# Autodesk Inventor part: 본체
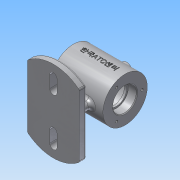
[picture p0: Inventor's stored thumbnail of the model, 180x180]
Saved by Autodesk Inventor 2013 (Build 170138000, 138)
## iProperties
Created: 2017-12
Part Number: 본체
Material: 알루미늄 6061
Document SubType Name: Modeling
Designer: Administrator
Density: 2.71 g/cm^3
Mass: 467.692 g
Surface Area: 486.473 cm^2
Volume: 172.58 cm^3
Author: Administrator
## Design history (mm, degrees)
sketch "스케치1"
  geometry: L1 (-35, 16)-(-23, 16); L2 (-23, 16)-(-23, 14); L3 (-23, 14)-(-20, 14); L4 (-20, 14)-(-20, 25); L5 (-20, 25)-(20, 25); L6 (20, 25)-(20, 14); L7 (20, 14)-(23, 14); L8 (23, 14)-(23, 16); L9 (23, 16)-(35, 16); L10 (35, 16)-(35, 30); L11 (35, 30)-(-35, 30); L12 (-35, 30)-(-35, 16); L13 (-49, 0)-(49, 0) reference; 1 further point
  constraints: 24 end point, 9 parallel, 1 collinear, 1 horizontal, 1 perpendicular
  dimensions: "d0" = 16 distance from line of L1 point (0, 0); "d1" = 14 distance from line of L3 point (0, 0); "d2" = 25 distance from line of L5 point (0, 0); "d3" = 14 distance from line of L7 point (0, 0); "d4" = 16 distance from line of L9 point (0, 0); "d5" = 70 distance of L10.end L11.end; "d6" = 12 distance of L1.start L1.end; "d7" = 3 distance of L2.end L3.end; "d8" = 40 distance of L4.end L5.end; "d9" = 3 distance of L6.end L7.end; "d10" = 30 distance from line of L11 point (0, 0); "d11" = 35 distance from line of L12 point (0, 0)
revolve "회전1" sketch "스케치1" stored, may be unused: angle "d12" = 90 deg
sketch "스케치2"
  geometry: C1 r 30 at (0, 0) reference; 1 further point
  constraints: 1 vertical alignment
  dimensions: "d13" = 23 distance of point (0, 23) C1.centre
hole "구멍1" sketch "스케치2" at (0, 23) diameter "d14" = 3.242; stored, may be unused: countersink angle "d18" = 90 deg, drill point angle "d20" = 118 deg; dims "d15" = 8, "d16" = 4, "d17" = 2, "d19" = 10
node "작업 평면1"
sketch "스케치3"
  geometry: C1 r 8 at (0, 0); 1 further point
  constraints: 1 centre point, 1 coincident
  dimensions: "d25" = 16 diameter of C1
extrude "돌출1" join sketch "스케치3" stored distance "d27" = 10; taper "d28" = 0 deg
hole "구멍2" diameter "d31" = 8; stored, may be unused: countersink angle "d35" = 90 deg, drill point angle "d37" = 118 deg; dims "d29" = 10, "d30" = 10, "d32" = 8, "d33" = 4, "d34" = 2, "d36" = 20
node "작업 평면2"
sketch "스케치4"
  geometry: L1 (35, 42.426)-(35, -42.426); L2 (-35, -42.426)-(-35, 42.426); C1 r 55 at (0, 0); A1 r 55 centre (0, 0) between (35, 42.426) and (-35, 42.426); A2 r 55 centre (0, 0) between (-35, -42.426) and (35, -42.426); 1 further point
  constraints: 4 end point, 4 point on circle, 3 centre point, 2 coincident, 1 parallel, 1 vertical
  dimensions: "d41" = 35 distance from line of L2 point (0, 0); "d42" = 70 distance between parallel lines of L1 L2; "d43" = 55 radius of A1; "d44" = 55 radius of A2; "d45" = 110 diameter of C1
extrude "돌출2" join sketch "스케치4" distance "d46" = 10; taper "d47" = 0 deg
sketch "스케치5"
  geometry: L1 (5, 40)-(5, 24); L2 (-5, 24)-(-5, 40); A1 r 55 centre (0, 0) between (-35, -42.426) and (35, -42.426) reference; A2 r 5 centre (0, 40) between (5, 40) and (-5, 40); A3 r 5 centre (0, 24) between (-5, 24) and (5, 24)
  constraints: 4 end point, 4 point on circle, 2 centre point, 2 tangent, 1 parallel, 1 vertical alignment
  dimensions: "d48" = 5 distance from line of L2 A1.centre; "d49" = 10 distance of L1.end L2.start; "d52" = 10 diameter of A2; "d53" = 10 diameter of A3; "d54" = 16 distance of A3.centre A2.centre; "d55" = 24 distance of A1.centre A3.centre
extrude "돌출3" cut sketch "스케치5" stored distance "d56" = 0; taper "d57" = 0 deg
sketch "스케치6"
  geometry: L1 (-15, 5)-(15, 5); L2 (15, -5)-(-15, -5); A1 r 55 centre (0, 0) between (-35, -42.426) and (35, -42.426) reference; A2 r 5 centre (-15, 0) between (-15, 5) and (-15, -5); A3 r 5 centre (15, 0) between (15, -5) and (15, 5)
  constraints: 4 end point, 4 point on circle, 2 centre point, 2 tangent, 1 horizontal, 1 parallel
  dimensions: "d61" = 10 distance of L2.end L1.start; "d62" = 5 distance from line of L1 A1.centre; "d63" = 10 diameter of A2; "d64" = 10 diameter of A3; "d65" = 30 distance of A2.centre A3.centre; "d66" = 15 distance of A2.centre A1.centre
extrude "돌출4" join sketch "스케치6" stored distance "d67" = 0; taper "d68" = 0 deg
chamfer "모따기1" distance "d69" = 1; stored, may be unused: second distance "d70" = 2, angle "d71" = 45 deg
fillet "모깎기1" dims "d72" = 5
fillet "모깎기2" dims "d73" = 3
fillet "모깎기3" dims "d74" = 0.3
node "작업 평면3"
sketch "스케치8"
  geometry: L1 (-26.203, 13.016)-(26.888, 13.016); L2 (26.888, 13.016)-(26.888, -12.673); L3 (26.888, -12.673)-(-26.203, -12.673); L4 (-26.203, -12.673)-(-26.203, 13.016); 1 further point
  constraints: 2 other
feature "엠보싱1" sketch "스케치8" dims "d0" = 16, "d1" = 14, "d2" = 25, "d3" = 14, "d4" = 16, "d5" = 70, "d6" = 12, "d7" = 3, "d8" = 40, "d9" = 3, "d10" = 30, "d11" = 35, "d76" = 0.5, "d77" = 0
chamfer "모따기2" distance "d78" = 1; stored, may be unused: second distance "d79" = 2, angle "d80" = 45 deg
node "솔리드1"
pattern_circular "원형 패턴1" dims angle "d22" = 360 deg
mirror "대칭1"
mirror "대칭2"
other parameters: "d24" = 37, "d38" = -62
